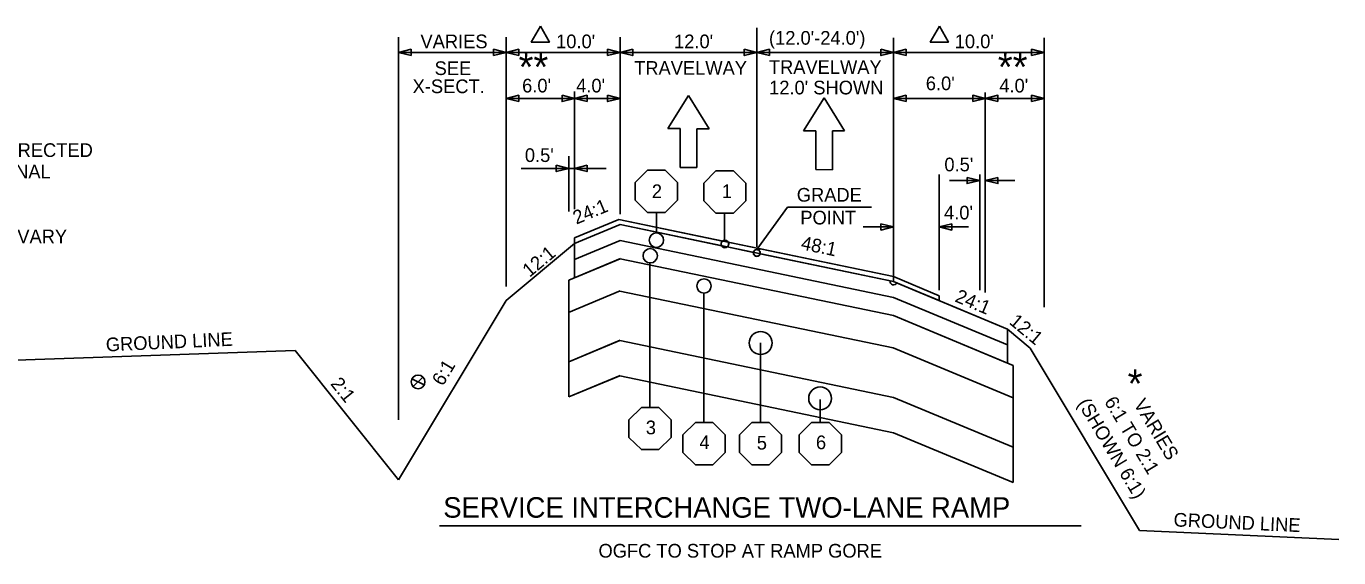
# Model space of a CAD drawing. Extents: x 4649 to 5578, y 4853 to 5383.
# Drawn here: x 5230.6 to 5345.7, y 5148.7 to 5195.3 of the extents above; entities that cross this region are included whole.
import ezdxf

# ---------------------------------------------------------------- set-up
doc = ezdxf.new("R2010")
doc.units = 0
for name, color, linetype in [('Level 2', 7, 'Continuous'), ('Level 25', 7, 'Continuous'), ('RD_QTY_OGFC', 7, 'Continuous'), ('RD_SHT_Bndy', 7, 'Continuous'), ('RD_SHT_Typical', 7, 'Continuous'), ('RD_Sketch1', 7, 'Continuous'), ('RD_Sketch2', 7, 'Continuous'), ('RD_TX_TypSect', 7, 'Continuous'), ('RD_XS_Base', 7, 'Continuous'), ('RD_XS_EarthShd', 7, 'Continuous')]:
    doc.layers.add(name, color=color, linetype=linetype)

msp = doc.modelspace()

# ---------------------------------------------------------------- linework, layer by layer
at = {"layer": 'Level 2'}
for p, q in [((5278.65, 5173.23), (5278.65, 5173.23)), ((5278.65, 5173.17), (5278.65, 5173.17))]:
    msp.add_line(p, q, dxfattribs=at)
at = {"layer": 'Level 25'}
for p, q in [((5297.34, 5179.41), (5294.67, 5175.71)), ((5304.73, 5179.41), (5297.34, 5179.41))]:
    msp.add_line(p, q, dxfattribs=at)
at = {"layer": 'RD_QTY_OGFC'}
for p, q in [((5282.56, 5178.34), (5278.67, 5176.72)), ((5278.67, 5176.22), (5282.67, 5177.89)), ((5291.65, 5176.44), (5282.56, 5178.34)), ((5282.67, 5177.89), (5291.57, 5176.03)), ((5278.67, 5176.72), (5278.67, 5176.22))]:
    msp.add_line(p, q, dxfattribs=at)
msp.add_arc((5291.86, 5176.19), 0.332, 129.1992, 207.7584, dxfattribs=at)
at = {"layer": 'RD_SHT_Bndy'}
for p, q in [((5286.86, 5186.31), (5288.68, 5189.22)), ((5288.68, 5189.22), (5290.47, 5186.3)), ((5298.76, 5186.11), (5300.58, 5189.02)), ((5300.58, 5189.02), (5302.36, 5186.1)), ((5287.95, 5186.31), (5286.86, 5186.31)), ((5287.95, 5186.31), (5287.95, 5182.91)), ((5289.41, 5186.3), (5290.47, 5186.3)), ((5289.41, 5186.3), (5289.41, 5182.9)), ((5299.85, 5186.11), (5298.76, 5186.11)), ((5299.85, 5186.11), (5299.85, 5182.71)), ((5301.3, 5186.1), (5302.36, 5186.1)), ((5301.3, 5186.1), (5301.3, 5182.7)), ((5287.95, 5182.91), (5289.41, 5182.9)), ((5299.85, 5182.71), (5301.3, 5182.7))]:
    msp.add_line(p, q, dxfattribs=at)
at = {"layer": 'RD_SHT_Typical'}
for p, q in [((5278.67, 5176.72), (5282.56, 5178.34)), ((5278.67, 5176.22), (5282.67, 5177.89)), ((5278.67, 5176.22), (5278.67, 5176.72)), ((5278.67, 5176.22), (5272.67, 5171.22)), ((5278.67, 5174.82), (5282.67, 5176.49)), ((5278.67, 5176.22), (5278.67, 5173.23)), ((5292.07, 5175.93), (5294.37, 5175.45)), ((5294.98, 5175.75), (5292.15, 5176.34)), ((5294.85, 5175.62), (5294.98, 5175.75)), ((5294.98, 5175.75), (5294.85, 5175.62)), ((5306.66, 5173.32), (5294.98, 5175.75)), ((5278.17, 5173.02), (5282.69, 5174.9)), ((5294.96, 5175.33), (5306.36, 5172.95)), ((5310.66, 5171.65), (5306.66, 5173.32)), ((5310.66, 5171.65), (5306.66, 5173.32)), ((5278.17, 5173.02), (5278.17, 5162.77)), ((5306.36, 5172.95), (5306.66, 5172.89)), ((5316.65, 5168.72), (5306.66, 5172.89)), ((5272.67, 5171.22), (5263.23, 5155.48)), ((5278.14, 5170.18), (5282.66, 5172.07)), ((5316.65, 5167.33), (5306.66, 5171.49)), ((5310.66, 5171.65), (5310.66, 5171.22)), ((5310.66, 5171.22), (5310.66, 5171.65)), ((5317.15, 5165.52), (5306.66, 5169.9)), ((5316.65, 5168.72), (5318.65, 5167.04)), ((5316.65, 5168.71), (5316.65, 5165.73)), ((5278.17, 5165.86), (5282.67, 5167.74)), ((5254.14, 5166.84), (5263.23, 5155.48)), ((5317.15, 5162.68), (5306.63, 5167.06)), ((5318.65, 5167.04), (5328.25, 5151.05)), ((5317.15, 5165.52), (5317.15, 5155.25)), ((5278.17, 5162.77), (5282.66, 5164.64)), ((5317.15, 5158.35), (5306.66, 5162.72)), ((5317.15, 5155.25), (5306.66, 5159.63))]:
    msp.add_line(p, q, dxfattribs=at)
for points in [[(5282.56, 5178.34), (5306.66, 5173.32)], [(5282.67, 5177.89), (5306.66, 5172.89)], [(5282.67, 5176.49), (5306.66, 5171.49)], [(5294.85, 5175.62), (5294.85, 5175.62)], [(5282.67, 5174.89), (5306.66, 5169.9)], [(5306.66, 5172.89), (5306.93, 5172.77), (5310.66, 5171.22)], [(5282.64, 5172.06), (5306.63, 5167.06)], [(5310.66, 5171.22), (5310.66, 5171.22)], [(5282.64, 5167.73), (5306.66, 5162.72)], [(5282.64, 5164.63), (5306.66, 5159.63)]]:
    msp.add_lwpolyline(points, dxfattribs=at)
for centre, radius, start, end in [((5291.86, 5176.19), 0.332, 308.7054, 27.2647), ((5294.66, 5175.39), 0.3, 50.3383, 168.2319), ((5294.66, 5175.39), 0.3, 348.2319, 50.3383)]:
    msp.add_arc(centre, radius, start, end, dxfattribs=at)
at = {"layer": 'RD_Sketch1'}
for p, q in [((5227.75, 5165.93), (5254.14, 5166.84)), ((5328.25, 5151.05), (5345.72, 5150.25))]:
    msp.add_line(p, q, dxfattribs=at)
at = {"layer": 'RD_Sketch2'}
for points in [[(5287.69, 5181.57), (5287.69, 5180.04), (5286.61, 5178.96), (5285.08, 5178.96), (5284, 5180.04), (5284, 5181.57), (5285.08, 5182.65), (5286.61, 5182.65)], [(5293.69, 5181.51), (5293.69, 5179.98), (5292.61, 5178.9), (5291.08, 5178.9), (5290, 5179.98), (5290, 5181.51), (5291.08, 5182.59), (5292.61, 5182.59)], [(5287.14, 5160.75), (5287.14, 5159.22), (5286.06, 5158.14), (5284.53, 5158.14), (5283.44, 5159.22), (5283.44, 5160.75), (5284.53, 5161.83), (5286.06, 5161.83)], [(5291.88, 5159.43), (5291.88, 5157.9), (5290.79, 5156.82), (5289.27, 5156.82), (5288.18, 5157.9), (5288.18, 5159.43), (5289.27, 5160.51), (5290.79, 5160.51)], [(5296.84, 5159.43), (5296.84, 5157.9), (5295.76, 5156.82), (5294.23, 5156.82), (5293.15, 5157.9), (5293.15, 5159.43), (5294.23, 5160.51), (5295.76, 5160.51)], [(5302.08, 5159.43), (5302.08, 5157.9), (5301, 5156.82), (5299.47, 5156.82), (5298.39, 5157.9), (5298.39, 5159.43), (5299.47, 5160.51), (5301, 5160.51)]]:
    msp.add_lwpolyline(points, close=True, dxfattribs=at)
at = {"layer": 'RD_TX_TypSect'}
for p, q in [((5294.66, 5195.16), (5294.66, 5175.94)), ((5263.23, 5160.77), (5263.23, 5194.32)), ((5272.67, 5172.47), (5272.67, 5194.32)), ((5282.67, 5178.8), (5282.67, 5194.32)), ((5282.67, 5194.28), (5282.67, 5183.82)), ((5306.66, 5194.28), (5306.66, 5172.89)), ((5319.87, 5194.28), (5319.87, 5170.63)), ((5263.23, 5192.99), (5272.67, 5192.99)), ((5272.67, 5192.99), (5282.67, 5192.99)), ((5282.67, 5192.99), (5294.66, 5192.99)), ((5294.66, 5192.99), (5306.66, 5192.99)), ((5306.66, 5192.99), (5319.87, 5192.99)), ((5278.67, 5179.25), (5278.67, 5189.57)), ((5314.71, 5171.93), (5314.71, 5189.49)), ((5272.67, 5188.96), (5278.67, 5188.96)), ((5278.67, 5188.96), (5282.67, 5188.96)), ((5306.66, 5188.96), (5314.71, 5188.96)), ((5314.71, 5188.96), (5319.87, 5188.96)), ((5278.17, 5179.03), (5278.17, 5183.9)), ((5273.99, 5182.82), (5278.17, 5182.82)), ((5281.43, 5182.82), (5278.17, 5182.82)), ((5310.66, 5182.29), (5310.66, 5172.14)), ((5311.56, 5181.75), (5314.22, 5181.75)), ((5314.22, 5182.29), (5314.22, 5172.14)), ((5317.29, 5181.75), (5314.71, 5181.75)), ((5285.85, 5178.96), (5285.85, 5177.16)), ((5291.84, 5176.52), (5291.84, 5178.9)), ((5304, 5177.68), (5306.66, 5177.68)), ((5313.23, 5177.68), (5310.66, 5177.68)), ((5285.27, 5161.84), (5285.27, 5174.52)), ((5290.01, 5160.51), (5290.01, 5171.87)), ((5306.66, 5162.72), (5282.65, 5167.73)), ((5294.98, 5160.51), (5294.98, 5167.52)), ((5278.17, 5165.86), (5278.17, 5162.77)), ((5264.4, 5164.36), (5265.47, 5163.82)), ((5264.52, 5163.67), (5265.35, 5164.51)), ((5278.17, 5162.77), (5282.64, 5164.63)), ((5282.64, 5164.63), (5306.66, 5159.63)), ((5300.22, 5160.51), (5300.22, 5162.54)), ((5317.15, 5158.35), (5306.66, 5162.72)), ((5306.66, 5159.63), (5317.15, 5155.25)), ((5317.15, 5155.25), (5317.15, 5158.35)), ((5266.82, 5151.47), (5323.13, 5151.47))]:
    msp.add_line(p, q, dxfattribs=at)
for points in [[(5275.67, 5195.29), (5274.87, 5193.9), (5276.47, 5193.9)], [(5310.68, 5195.29), (5309.88, 5193.9), (5311.48, 5193.9)], [(5264.33, 5192.72), (5264.33, 5193.27), (5263.23, 5192.99)], [(5271.57, 5192.72), (5271.57, 5193.27), (5272.67, 5192.99)], [(5273.77, 5192.72), (5273.77, 5193.27), (5272.67, 5192.99)], [(5281.56, 5192.72), (5281.56, 5193.27), (5282.67, 5192.99)], [(5283.77, 5193.27), (5283.77, 5192.72), (5282.67, 5192.99)], [(5293.56, 5193.27), (5293.56, 5192.72), (5294.66, 5192.99)], [(5295.77, 5192.72), (5295.77, 5193.27), (5294.66, 5192.99)], [(5305.55, 5193.27), (5305.55, 5192.72), (5306.66, 5192.99)], [(5307.76, 5192.72), (5307.76, 5193.27), (5306.66, 5192.99)], [(5318.77, 5192.72), (5318.77, 5193.27), (5319.87, 5192.99)], [(5273.77, 5188.68), (5273.77, 5189.23), (5272.67, 5188.96)], [(5277.57, 5189.23), (5277.57, 5188.68), (5278.67, 5188.96)], [(5279.77, 5188.68), (5279.77, 5189.23), (5278.67, 5188.96)], [(5281.56, 5189.23), (5281.56, 5188.68), (5282.67, 5188.96)], [(5307.76, 5188.68), (5307.76, 5189.23), (5306.66, 5188.96)], [(5313.61, 5188.68), (5313.61, 5189.23), (5314.71, 5188.96)], [(5315.82, 5188.68), (5315.82, 5189.23), (5314.71, 5188.96)], [(5318.77, 5188.68), (5318.77, 5189.23), (5319.87, 5188.96)], [(5277.07, 5183.09), (5277.07, 5182.54), (5278.17, 5182.82)], [(5279.77, 5183.09), (5279.77, 5182.54), (5278.67, 5182.82)], [(5313.11, 5182.03), (5313.11, 5181.48), (5314.22, 5181.75)], [(5315.82, 5182.03), (5315.82, 5181.48), (5314.71, 5181.75)], [(5305.55, 5177.96), (5305.55, 5177.41), (5306.66, 5177.68)], [(5311.76, 5177.96), (5311.76, 5177.41), (5310.66, 5177.68)]]:
    msp.add_lwpolyline(points, close=True, dxfattribs=at)
msp.add_lwpolyline([(5282.65, 5167.73), (5282.64, 5167.72), (5278.17, 5165.86)], dxfattribs=at)
for centre, radius in [((5285.85, 5176.52), 0.63), ((5285.31, 5175.15), 0.63), ((5291.86, 5176.19), 0.332), ((5294.66, 5175.39), 0.3), ((5294.67, 5175.41), 0.3), ((5290.03, 5172.5), 0.63), ((5295, 5167.5), 1), ((5264.94, 5164.09), 0.6), ((5300.22, 5162.64), 1), ((5300.22, 5162.64), 1)]:
    msp.add_circle(centre, radius, dxfattribs=at)
at = {"layer": 'RD_XS_Base'}
for p, q in [((5282.67, 5177.89), (5278.67, 5176.22)), ((5306.36, 5172.95), (5282.67, 5177.89)), ((5278.67, 5174.82), (5282.67, 5176.49)), ((5278.67, 5176.22), (5278.67, 5174.82)), ((5282.67, 5176.49), (5306.66, 5171.49)), ((5316.65, 5168.71), (5306.93, 5172.77)), ((5306.66, 5171.49), (5316.65, 5167.33)), ((5316.65, 5167.33), (5316.65, 5168.71))]:
    msp.add_line(p, q, dxfattribs=at)
msp.add_circle((5285.85, 5176.52), 0.63, dxfattribs=at)
msp.add_arc((5306.66, 5172.89), 0.3, 168.2319, 337.3117, dxfattribs=at)
at = {"layer": 'RD_XS_EarthShd'}
for p, q in [((5282.67, 5176.49), (5278.67, 5174.82)), ((5306.66, 5171.49), (5282.67, 5176.49)), ((5278.67, 5173.23), (5282.67, 5174.89)), ((5278.67, 5174.82), (5278.67, 5173.23)), ((5282.67, 5174.89), (5306.66, 5169.9)), ((5316.65, 5167.33), (5306.66, 5171.49)), ((5306.66, 5169.9), (5316.65, 5165.73)), ((5316.65, 5165.73), (5316.65, 5167.33))]:
    msp.add_line(p, q, dxfattribs=at)

# ---------------------------------------------------------------- texts
at = {"layer": 'RD_TX_TypSect'}
for s, height, p in [('VARIES', 1.2, (5265.15, 5193.36)), ("10.0'", 1.2, (5277.05, 5193.36)), ("12.0'", 1.2, (5287.4, 5193.36)), ("10.0'", 1.2, (5312.03, 5193.36)), ('**', 2.5, (5273.76, 5190.47)), ('**', 2.5, (5315.81, 5190.47)), ('SEE', 1.2, (5266.39, 5191.01)), ('TRAVELWAY', 1.2, (5283.9, 5191.03)), ('X-SECT.', 1.2, (5264.46, 5189.42)), ("6.0'", 1.2, (5274.07, 5189.48)), ("4.0'", 1.2, (5278.81, 5189.48)), ("6.0'", 1.2, (5309.49, 5189.68)), ("4.0'", 1.2, (5315.94, 5189.48)), ("0.5'", 1.2, (5274.31, 5183.38)), ("0.5'", 1.2, (5311.12, 5182.56)), ('2', 1.2, (5285.45, 5180.21)), ('1', 1.2, (5291.59, 5180.22)), ('GRADE', 1.2, (5298.17, 5179.9)), ('POINT', 1.2, (5298.48, 5177.9)), ("4.0'", 1.2, (5311.09, 5178.34)), ('PAVED AND EARTH SHOULDERS VARY ', 1.1999, (5203.74, 5176.25)), ('*', 2.5, (5327.2, 5162.69)), ('3', 1.2, (5284.92, 5159.49)), ('4', 1.2, (5289.63, 5158.2)), ('5', 1.2, (5294.66, 5158.15)), ('6', 1.2, (5299.85, 5158.18)), ('SERVICE INTERCHANGE TWO-LANE RAMP', 1.8, (5267.15, 5152.17)), ('OGFC TO STOP AT RAMP GORE', 1.2, (5280.77, 5148.67))]:
    msp.add_text(s, height=height, dxfattribs=at).set_placement(p)
for s, height, rotation, p in [("(12.0'-24.0')", 1.2, 0.0016, (5295.73, 5193.67)), ('TRAVELWAY', 1.2, 0.0016, (5295.72, 5191.11)), ("12.0' SHOWN", 1.2, 0.0016, (5295.74, 5189.31)), ("ADD 3.5' WHERE GUARDRAIL IS ERECTED ", 1.1999, 360, (5203.73, 5183.82)), ('EXCEPT IN AREAS WITH ADDITIONAL ', 1.1999, 360, (5203.73, 5181.94)), ('24:1', 1.2, 22.619, (5278.83, 5177.88)), ('48:1', 1.2, 348.2317, (5298.47, 5175.73)), ('12:1', 1.2, 39.8056, (5274.72, 5173.21)), ('24:1', 1.2, 337.3801, (5311.97, 5171.16)), ('12:1', 1.2, 320.1939, (5316.73, 5169.24)), ('GROUND LINE', 1.2, 2.6095, (5237.57, 5166.75)), ('6:1', 1.2, 59.0362, (5267.11, 5163.65)), ('2:1', 1.2, 308.6598, (5257.2, 5163.9)), ('(SHOWN 6:1)', 1.2, 300.9638, (5322.76, 5162.2)), ('6:1 TO 2:1', 1.2, 300.9638, (5325.11, 5162.36)), ('VARIES', 1.2, 300.9638, (5327.69, 5162.15)), ('GROUND LINE', 1.2, 357.3905, (5331.21, 5151.41))]:
    msp.add_text(s, height=height, rotation=rotation, dxfattribs=at).set_placement(p)

doc.saveas('drawing.dxf')
